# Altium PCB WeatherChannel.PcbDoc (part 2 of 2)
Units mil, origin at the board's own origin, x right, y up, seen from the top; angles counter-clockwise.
Board outline 4050 x 7300 mil, 2 copper layers (Top Layer, Bottom Layer); 129 components, 144 nets, 770 pads, 170 vias.
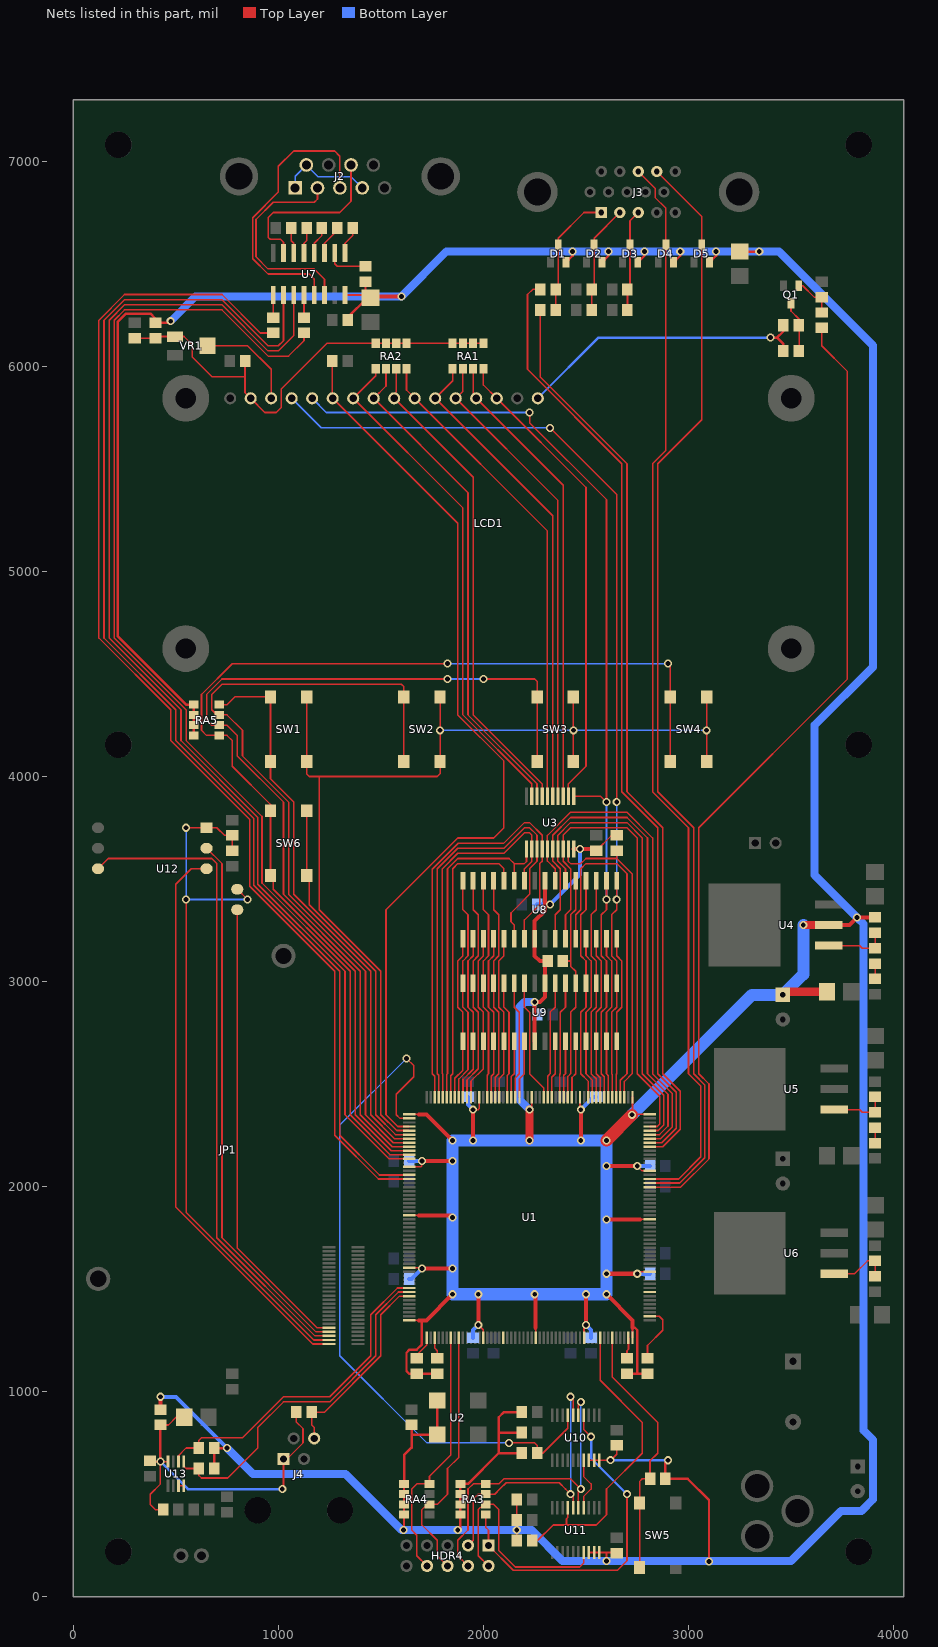
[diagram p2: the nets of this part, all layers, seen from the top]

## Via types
v1: diameter 39.37, hole 23.62, Top Layer to Bottom Layer, 170 vias

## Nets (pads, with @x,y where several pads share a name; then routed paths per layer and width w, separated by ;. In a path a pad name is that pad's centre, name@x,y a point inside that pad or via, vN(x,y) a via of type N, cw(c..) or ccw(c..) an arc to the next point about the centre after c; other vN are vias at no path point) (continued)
JTAG_NEXUS_TDO: HDR4.6 RA4.2 U1.165 | length 1294.2
  Top Layer w7.87: HDR4.6@1825,175 HDR4.6@1825,150 1775,200 1775,275 1700,350 1700,425 1725,450 RA4.2@1737,450 1775,450 1825,500 1825,625 1880.51,680.51 U1.165@1880.51,1263.39
JTAG_NEXUS_TMS: HDR4.8 RA4.4 U1.163 | length 1259.9
  Top Layer w7.87: HDR4.8@1725,150 1675,200 1675,300 1650,325 1650,525 1675,550 RA4.4@1737,550 1737,587 1841.14,691.14 U1.163@1841.14,1263.39
KP_COL0: RA5.4 SW1.3 SW1.4 U1.111 | length 2742.1
  Top Layer w7.87: RA5.4@712,4350 750,4350 787.87,4387.87 SW1.3@961.81,4387.87 SW1.4@961.81,4072.52 961.81,3988.19 1075,3875 1075,3425 1450,3050 1450,2375 1450,2350 1566.14,2233.86 U1.111@1638.39,2233.86
KP_COL1: RA5.3 SW2.3 SW2.4 U1.112 | length 3987.7
  Top Layer w7.87: SW2.4@1611.81,4072.52 SW2.3@1611.81,4387.87 1611.81,4438.19 1600,4450 725,4450 675,4400 675,4325 700,4300 RA5.3@712,4300 750,4300 825,4225 825,4100 1050,3875 1050,3425 1425,3050 1425,2375 1425,2350 1560.83,2214.17 U1.112@1638.39,2214.17
KP_COL2: RA5.2 SW3.3 SW3.4 U1.113 | length 4745.8
  Top Layer w7.87: U1.113@1638.39,2194.49 1555.51,2194.49 1400,2350 1400,2375 1400,3050 1025,3425 1025,3875 800,4100 800,4200 750,4250 RA5.2@712,4250 675,4250 650,4275 650,4400 725,4475 v1(1825,4475) ; v1(2000,4475) 2250,4475 2261.81,4463.19 SW3.3@2261.81,4387.87 SW3.4@2261.81,4072.52
  Bottom Layer w7.87: v1(1825,4475) v1(2000,4475)
KP_COL3: RA5.1 SW4.3 SW4.4 SW6.3 SW6.4 U1.114 | length 5574.7
  Top Layer w7.87: SW6.4@961.81,3517.52 975,3504.33 975,3450 1375,3050 1375,2375 1375,2350 1550.2,2174.8 U1.114@1638.39,2174.8 ; SW6.4@961.81,3522.52 SW6.3@961.81,3837.87 ; SW6.3@961.81,3832.87 961.81,3863.19 775,4050 775,4175 750,4200 RA5.1@712,4200 650,4200 625,4225 625,4400 775,4550 v1(1825,4550) ; v1(2900,4550) 2911.81,4538.19 SW4.3@2911.81,4387.87 SW4.4@2911.81,4072.52
  Bottom Layer w7.87: v1(1825,4550) v1(2900,4550)
KP_ROW0: SW1.1 SW1.2 SW2.1 SW2.2 SW3.1 SW3.2 SW4.1 SW4.2 U1.109 | length 5286.3
  Top Layer w7.87: SW1.1@1138.58,4387.87 SW1.2@1138.58,4072.52 1138.58,4011.42 1150,4000 1775,4000 1788.58,4013.58 SW2.2@1788.58,4072.52 SW2.1@1788.58,4387.87 ; 1200,4000 1200,3350 1500,3050 1500,2375 1500,2350 1576.77,2273.23 U1.109@1638.39,2273.23 ; SW3.2@2438.58,4072.52 SW3.1@2438.58,4387.87 ; SW4.2@3088.58,4072.52 SW4.1@3088.58,4387.87
  Bottom Layer w7.87: v1(1788.58,4225) v1(2438.58,4225) v1(3088.58,4225)
KP_ROW1: U1.8
KP_ROW2: U1.176
KP_ROW3: SW6.1 SW6.2 U1.110 | length 1825.6
  Top Layer w7.87: SW6.2@1138.58,3517.52 1150,3506.1 1150,3375 1475,3050 1475,2375 1475,2350 1571.46,2253.54 U1.110@1638.39,2253.54 ; SW6.2@1138.58,3522.52 SW6.1@1138.58,3837.87
LCD_BCKL: R9.1 U1.34 | length 4770.7
  Top Layer w7.87: U1.34@2811.61,1997.64 2962.64,1997.64 3100,2135 3100,2500 3050,2550 3050,3750 3775,4475 3775,5975 3650,6100 R9.1@3650,6187.6
LCD_D0: LCD1.7 RA2.1 U3.9 | length 2490.2
  Top Layer w7.87: RA2.1@1475,5988 1475,5954 LCD1.7@1365,5844 1900,5309 1900,4300 2235.43,3964.57 U3.9@2235.43,3903.94
LCD_D1: LCD1.8 RA2.2 U3.8 | length 2438.6
  Top Layer w7.87: RA2.2@1525,5988 1525,5904 LCD1.8@1465,5844 1925,5384 1925,4300 2261.02,3963.98 U3.8@2261.02,3903.94
LCD_D2: LCD1.9 RA2.3 U3.7 | length 2387.3
  Top Layer w7.87: LCD1.9@1550,5850 1575,5875 RA2.3@1575,5988 ; LCD1.9@1565,5844 1950,5459 1950,4300 2286.61,3963.39 U3.7@2286.61,3903.94
LCD_D3: LCD1.10 RA2.4 U3.6 | length 2368.7
  Top Layer w7.87: RA2.4@1625,5988 1625,5884 LCD1.10@1665,5844 2312.2,5196.8 U3.6@2312.2,3903.94
LCD_D4: LCD1.11 RA1.1 U3.5 | length 2356.5
  Top Layer w7.87: RA1.1@1850,5988 1850,5929 LCD1.11@1765,5844 2337.8,5271.2 U3.5@2337.8,3903.94
LCD_D5: LCD1.12 RA1.2 U3.4 | length 2305
  Top Layer w7.87: RA1.2@1900,5988 1900,5879 LCD1.12@1865,5844 2363.39,5345.61 U3.4@2363.39,3903.94
LCD_D6: LCD1.13 RA1.3 U3.3 | length 2265.9
  Top Layer w7.87: RA1.3@1950,5988 1950,5859 LCD1.13@1965,5844 2388.98,5420.02 U3.3@2388.98,3903.94
LCD_D7: LCD1.14 RA1.4 U3.2 | length 2326.6
  Top Layer w7.87: RA1.4@2000,5988 2000,5909 LCD1.14@2065,5844 2500,5409 2500,4050 2414.57,3964.57 U3.2@2414.57,3903.94
LCD_E: LCD1.6 R5.1 U1.108 | length 4496.2
  Top Layer w7.87: LCD1.6@1262.6,5846.4 R5.1@1262.6,6025 ; LCD1.6@1265,5844 1875,5234 1875,4300 2100,4075 2100,3750 2050,3700 1875,3700 1725,3550 1525,3350 1525,2350 1582.09,2292.91 U1.108@1638.39,2292.91
LCD_EDATA: R6.1 U1.55 U3.19 | length 1558.3
  Top Layer w7.87: U3.19@2414.57,3646.06 2414.57,3585.43 2425,3575 2475,3575 2500,3600 2650,3600 ; R6.1@2650,3637.6 2650,3600 ; U1.55@2687.6,2436.61 2687.6,2512.6 2725,2550 2725,3525 2650,3600
NetC14_1: C14.1 U7.1 | length 138.1
  Top Layer w7.87: U7.1@1325,6552.36 1325,6600 1362.4,6637.4 C14.1@1362.4,6675
NetC14_2: C14.2 U7.3 | length 148.6
  Top Layer w7.87: U7.3@1225,6552.36 1225,6600 1287.6,6662.6 C14.2@1287.6,6675
NetC15_2: C15.2 U7.2 | length 207.6
  Top Layer w7.87: U7.2@1275,6552.36 1275,6500 1287.6,6487.4 C15.2@1425,6487.4
NetC16_1: C16.1 U7.4 | length 138.1
  Top Layer w7.87: U7.4@1175,6552.36 1175,6600 1212.4,6637.4 C16.1@1212.4,6675
NetC16_2: C16.2 U7.5 | length 127.9
  Top Layer w7.87: U7.5@1125,6552.36 1125,6600 1137.6,6612.6 C16.2@1137.6,6675
NetC17_1: C17.1 U7.6 | length 127.9
  Top Layer w7.87: C17.1@1062.4,6675 1062.4,6612.6 1075,6600 U7.6@1075,6552.36
NetC41_1: C41.1 C42.1 JP1.2 U12.1 U12.7 | length 3516.3
  Top Layer w7.87: v1(550,3400) 550,1875 1173.03,1251.97 JP1.2@1246.46,1251.97 ; v1(550,3750) U12.1@650,3750 700,3750 737.4,3712.6 C42.1@775,3712.6 C41.1@775,3637.4 ; U12.7@799.61,3450 849.61,3400 v1(850,3400)
  Bottom Layer w7.87: v1(550,3750) v1(550,3400) v1(850,3400)
NetD1_3: D1.3 J3.1 R31.2 R34.2 | length 617
  Top Layer w7.87: R31.2@2352.4,6275 R34.2@2352.4,6375 2365,6387.6 D1.3@2365,6593.31 2365,6625 2490,6750 J3.1@2575,6750
NetD2_3: D2.3 J3.2 R32.2 R35.2 | length 532.1
  Top Layer w7.87: R32.2@2527.4,6275 R35.2@2527.4,6375 2540,6387.6 D2.3@2540,6593.31 2540,6624.84 J3.2@2665.16,6750
NetD3_3: D3.3 J3.3 R33.2 R36.2 | length 496.9
  Top Layer w7.87: R33.2@2702.4,6275 R36.2@2702.4,6375 2715,6387.6 D3.3@2715,6593.31 2715,6709.68 J3.3@2755.32,6750
NetJ2_1: J2.1 J2.4 J2.6 | length 457.5
  Bottom Layer w7.87: J2.1@1081.89,6870.08 1081.89,6927.36 J2.6@1136.42,6981.89 1193.31,6925 1354.13,6925 J2.4@1409.05,6870.08 ; J2.1@1104.92,6845.08 J2.1@1109.05,6845.08
NetJP1_1: JP1.1 U12.3 | length 2779.1
  Top Layer w7.87: U12.3@650,3550 575,3550 500,3475 500,1900 1167.72,1232.28 JP1.1@1246.46,1232.28
NetJP1_3: JP1.3 U12.6 | length 3180.2
  Top Layer w7.87: U12.6@120.47,3550 170.47,3600 675,3600 700,3575 700,1750 1178.35,1271.65 JP1.3@1246.46,1271.65
NetJP1_4: JP1.4 U12.2 | length 2642.5
  Top Layer w7.87: U12.2@650,3650 725,3575 725,1750 1183.66,1291.34 JP1.4@1246.46,1291.34
NetJP1_5: JP1.5 U12.8 | length 2257.7
  Top Layer w7.87: U12.8@799.61,3350 799.61,1700.39 1188.98,1311.02 JP1.5@1246.46,1311.02
NetLCD1_3: LCD1.3 VR1.W | length 499.9
  Top Layer w7.87: VR1.W@653.74,6100 850,6100 965,5985 LCD1.3@965,5844
NetLCD1_16: LCD1.16 R7.1 R8.1 | length 1454
  Top Layer w11.81: v1@3410,6150 v1(3400,6140) 3431.5,6140 ; R8.1@3462.6,6075 3462.6,6108.9 3431.5,6140 ; R7.1@3462.6,6200 3462.6,6171.1 3431.5,6140
  Bottom Layer w11.81: LCD1.16@2265,5844 2561,6140 v1(3400,6140)
NetQ1_1: Q1.1 R9.2 R10.2 | length 210.9
  Top Layer w7.87: Q1.1@3537.4,6393.31 3556.69,6393.31 3612.4,6337.6 R10.2@3650,6337.6 R9.2@3650,6262.4
NetQ1_3: Q1.3 R7.2 R8.2 | length 248.3
  Top Layer w7.87: Q1.3@3500,6306.69 3500,6269.29 3540,6229.29 3540,6197.4 R8.2@3540,6075
NetR13_2: R13.2 R16.1 U4.1 | length 305.4
  Top Layer w7.87: U4.1@3685,3175 3835,3175 3847.6,3162.4 R16.1@3910,3162.4 R13.2@3910,3237.6
NetR14_2: R14.2 R18.1 U5.1 | length 280.4
  Top Layer w7.87: U5.1@3710,2375 3835,2375 3847.6,2362.4 R18.1@3910,2362.4 R14.2@3910,2437.6
NetR15_2: R15.2 R20.1 U6.1 | length 301.1
  Top Layer w7.87: U6.1@3710,1575 3810,1575 3872.6,1637.6 R15.2@3910,1637.6 R20.1@3910,1562.4
NetR16_2: R16.2 R17.1 | length 75.2
  Top Layer w7.87: R17.1@3910,3012.4 R16.2@3910,3087.6
NetR18_2: R18.2 R19.1 | length 75.2
  Top Layer w7.87: R19.1@3910,2212.4 R18.2@3910,2287.6
NetR21_2: R21.2 U7.12 | length 110.2
  Top Layer w7.87: R21.2@1125,6237.4 U7.12@1125,6347.64
NetR22_2: R22.2 U7.9 | length 110.2
  Top Layer w7.87: R22.2@975,6237.4 U7.9@975,6347.64
NetU10_17: U10.17 U11.4 | length 261.8
  Top Layer w7.87: U11.4@2488.39,434.25 2488.39,488.39 2525,525 2525,550 2488.39,586.61 U10.17@2488.39,665.75
NetU13_3: U13.3 U13.4 | length 25.6
  Top Layer w7.87: U13.3@512.8,540.95 U13.4@538.39,540.95
PROGRAM: R26.2 U1.106 U10.7 | length 3423.5
  Top Layer w7.87: v1(1625,2625) 1660,2590 1660,2535 1575,2450 1575,2350 1592.72,2332.28 U1.106@1638.39,2332.28 ; v1(2125,750) 2250,750 2262.4,737.6 R26.2@2262.4,700 2290,700 2411.61,821.61 U10.7@2411.61,884.25
  Bottom Layer w7.87: v1(1625,2625) 1300,2300 1300,1175 1725,750 v1(2125,750)
PROGRAM_PR: R29.2 U1.200 U11.7 | length 1522.4
  Top Layer w7.87: R29.2@2237.4,275 2265,275 2340,350 2385,350 2550,350 2600,400 2600,525 2775,700 2775,850 2569.49,1055.51 U1.200@2569.49,1263.39 ; 2405,350 2405,380 2411.61,386.61 U11.7@2411.61,434.25
RAM0_DATA0: U1.99 U3.11 U8.11 | length 1679.3
  Top Layer w7.87: U1.99@1821.46,2436.61 1821.46,2546.46 1825,2550 1825,3550 1875,3600 2125,3600 2150,3575 ; U8.11@2150,3491.73 2150,3575 ; U3.11@2209.84,3646.06 2209.84,3584.84 2200,3575 2150,3575
RAM0_DATA1: U1.100 U3.12 U8.10 | length 1863.9
  Top Layer w7.87: U1.100@1801.77,2436.61 1801.77,2548.23 1800,2550 1800,3550 1875,3625 2100,3625 2200,3725 2225,3725 2235.43,3714.57 2235.43,3585.43 2200,3550 U8.10@2200,3491.73
RAM0_DATA2: U1.101 U3.13 U8.22 | length 2264.9
  Top Layer w7.87: U1.101@1782.09,2436.61 1782.09,2542.91 1775,2550 1775,3550 1875,3650 2100,3650 2200,3750 2225,3750 2261.02,3713.98 2261.02,3586.02 2225,3550 2225,3425 2134.25,3334.25 2134.25,3290.93 2150,3275.18 U8.22@2150,3208.27
RAM0_DATA3: U1.102 U3.14 U8.23 | length 2314.9
  Top Layer w7.87: U1.102@1762.4,2436.61 1762.4,2537.6 1750,2550 1750,3547.27 1875,3672.27 1875,3675 2100,3675 2200,3775 2225,3775 2286.61,3713.39 2286.61,3586.61 2275,3575 2275,3375 2200,3300 U8.23@2200,3208.27
RAM0_DATA4: U1.46 U3.15 U8.7 | length 2428.4
  Top Layer w7.87: U8.7@2350,3491.73 2350,3550 2312.2,3587.8 2312.2,3712.2 2425,3825 2700,3825 2825,3700 2825,2550 2920,2455 2920,2290 2863.86,2233.86 U1.46@2811.61,2233.86
RAM0_DATA5: U1.47 U3.16 U8.26 | length 2622
  Top Layer w7.87: U8.26@2350,3208.27 2350,3325 2375,3350 2375,3550 2337.8,3587.2 2337.8,3712.8 2425,3800 2700,3800 2800,3700 2800,2550 2900,2450 2900,2295 2858.54,2253.54 U1.47@2811.61,2253.54
RAM0_DATA6: U1.48 U3.17 U8.6 | length 2228
  Top Layer w7.87: U8.6@2400,3491.73 2400,3550 2363.39,3586.61 2363.39,3713.39 2425,3775 2700,3775 2775,3700 2775,2550 2880,2445 2880,2300 2853.23,2273.23 U1.48@2811.61,2273.23
RAM0_DATA7: U1.49 U3.18 U8.27 | length 2421.6
  Top Layer w7.87: U8.27@2400,3208.27 2400,3325 2425,3350 2425,3550 2388.98,3586.02 2388.98,3713.98 2425,3750 2700,3750 2750,3700 2750,2550 2860,2440 2860,2305 2847.91,2292.91 U1.49@2811.61,2292.91
RAM0_OE: U1.56 U8.28 | length 1709.8
  Top Layer w7.87: U8.28@2450,3208.27 2450,3325 2475,3350 2475,3550 2500,3575 2650,3575 2700,3525 2700,2550 2667.91,2517.91 U1.56@2667.91,2436.61
RAM0_WE: U1.98 U8.12 | length 1446
  Top Layer w7.87: U1.98@1841.14,2436.61 1841.14,2541.14 1850,2550 1850,3550 1875,3575 2075,3575 2100,3550 U8.12@2100,3491.73
RAM1_DATA0: U1.71 U9.6 | length 566.5
  Top Layer w7.87: U1.71@2372.64,2436.61 2372.64,2547.64 2375,2550 2375,2850 2400,2875 U9.6@2400,2991.73
RAM1_DATA1: U1.74 U9.7 | length 570.2
  Top Layer w7.87: U1.74@2313.58,2436.61 2313.58,2538.58 2325,2550 2325,2850 2350,2875 U9.7@2350,2991.73
RAM1_DATA2: U1.75 U9.10 | length 594
  Top Layer w7.87: U9.10@2200,2991.73 2200,2875 2225,2850 2225,2550 2293.9,2481.1 U1.75@2293.9,2436.61
RAM1_DATA3: U1.82 U9.11 | length 573.3
  Top Layer w7.87: U9.11@2150,2991.73 2150,2875 2175,2850 2175,2550 2156.1,2531.1 U1.82@2156.1,2436.61
RAM1_DATA4: U1.83 U9.22 | length 277.3
  Top Layer w7.87: U1.83@2136.42,2436.61 2136.42,2536.42 2150,2550 U9.22@2150,2708.27
RAM1_DATA5: U1.81 U9.23 | length 281.7
  Top Layer w7.87: U1.81@2175.79,2436.61 2175.79,2525.79 2200,2550 U9.23@2200,2708.27
RAM1_DATA6: U1.73 U9.26 | length 278.6
  Top Layer w7.87: U1.73@2333.27,2436.61 2333.27,2533.27 2350,2550 U9.26@2350,2708.27
RAM1_DATA7: U1.70 U9.27 | length 274.8
  Top Layer w7.87: U1.70@2392.32,2436.61 2392.32,2542.32 2400,2550 U9.27@2400,2708.27
RAM1_OE: U1.68 U9.28 | length 279.2
  Top Layer w7.87: U1.68@2431.69,2436.61 2431.69,2531.69 2450,2550 U9.28@2450,2708.27
RAM1_WE: U1.84 U9.12 | length 568.9
  Top Layer w7.87: U9.12@2100,2991.73 2100,2875 2125,2850 2125,2550 2116.73,2541.73 U1.84@2116.73,2436.61
RAM_ADDR0: LCD1.4 U1.58 U8.1 U9.1 | length 4841.9
  Top Layer w7.87: v1(2325,5700) 2650,5375 v1(2650,3875) ; U1.58@2628.54,2436.61 2628.54,2546.46 2625,2550 2625,2850 2650,2875 2650,3100 2625,3125 2625,3325 2650,3350 U8.1@2650,3491.73
  Bottom Layer w7.87: LCD1.4@1065,5844 1209,5700 v1(2325,5700) ; v1(2650,3400) v1(2650,3875)
RAM_ADDR1: LCD1.5 U1.60 U3.1 U8.2 U9.2 | length 4882.8
  Top Layer w7.87: v1(2225,5775) 2225,5725 2600,5350 v1(2600,3875) 2571.06,3903.94 U3.1@2440.16,3903.94 ; U1.60@2589.17,2436.61 2589.17,2535.83 2575,2550 2575,2850 2600,2875 2600,3100 2575,3125 2575,3325 2600,3350 U8.2@2600,3491.73
  Bottom Layer w7.87: LCD1.5@1165,5844 1234,5775 v1(2225,5775) ; v1(2600,3400) v1(2600,3875)
RAM_ADDR2: U1.62 U8.3 U9.3 | length 1096.5
  Top Layer w7.87: U1.62@2549.8,2436.61 2549.8,2525.2 2525,2550 2525,2850 2550,2875 2550,3100 2525,3125 2525,3325 2550,3350 U8.3@2550,3491.73
RAM_ADDR3: U1.64 U8.4 U9.4 | length 1100.9
  Top Layer w7.87: U8.4@2500,3491.73 2500,3350 2475,3325 2475,3125 2500,3100 2500,2875 2475,2850 2475,2550 2510.43,2514.57 U1.64@2510.43,2436.61
RAM_ADDR4: U1.87 U8.13 U9.13 | length 1093.4
  Top Layer w7.87: U8.13@2050,3491.73 2050,3350 2075,3325 2075,3125 2050,3100 2050,2875 2075,2850 2075,2550 2057.68,2532.68 U1.87@2057.68,2436.61
RAM_ADDR5: U1.89 U8.14 U9.14 | length 1089
  Top Layer w7.87: U8.14@2000,3491.73 2000,3350 2025,3325 2025,3125 2000,3100 2000,2875 2025,2850 2025,2550 2018.31,2543.31 U1.89@2018.31,2436.61
RAM_ADDR6: U1.94 U8.15 U9.15 | length 1109
  Top Layer w7.87: U1.94@1919.88,2436.61 1919.88,2519.88 1975,2575 1975,2850 1950,2875 1950,3100 1975,3125 1975,3325 1950,3350 U8.15@1950,3491.73
RAM_ADDR7: U1.96 U8.16 U9.16 | length 1112.9
  Top Layer w7.87: U1.96@1880.51,2436.61 1880.51,2525.05 1925,2569.54 1925,2850 1900,2875 1900,3100 1925,3125 1925,3325 1900,3350 U8.16@1900,3500
RAM_ADDR8: U1.97 U8.17 U9.17 | length 808.6
  Top Layer w7.87: U1.97@1860.83,2436.61 1860.83,2527.64 1900,2566.81 1900,2850 1875,2875 1875,3100 1900,3125 U8.17@1900,3208.27
RAM_ADDR9: U1.95 U8.18 U9.18 | length 813
  Top Layer w7.87: U1.95@1900.2,2436.61 1900.2,2522.47 1950,2572.27 1950,2850 1925,2875 1925,3100 1950,3125 U8.18@1950,3208.27
RAM_ADDR10: U1.93 U8.19 U9.19 | length 817.4
  Top Layer w7.87: U1.93@1939.57,2436.61 1939.57,2514.57 2000,2575 2000,2850 1975,2875 1975,3100 2000,3125 U8.19@2000,3208.27
RAM_ADDR11: U1.88 U8.20 U9.20 | length 797.3
  Top Layer w7.87: U1.88@2037.99,2436.61 2037.99,2537.99 2050,2550 2050,2850 2025,2875 2025,3100 2050,3125 U8.20@2050,3208.27
RAM_ADDR12: U1.86 U8.21 U9.21 | length 801.7
  Top Layer w7.87: U1.86@2077.36,2436.61 2077.36,2527.36 2100,2550 2100,2850 2075,2875 2075,3100 2100,3125 U8.21@2100,3208.27
RAM_ADDR13: U1.63 U8.29 U9.29 | length 804.8
  Top Layer w7.87: U8.29@2500,3208.27 2500,3125 2525,3100 2525,2875 2500,2850 2500,2550 2530.12,2519.88 U1.63@2530.12,2436.61
RAM_ADDR14: U1.61 U8.30 U9.30 | length 800.4
  Top Layer w7.87: U8.30@2550,3208.27 2550,3125 2575,3100 2575,2875 2550,2850 2550,2550 2569.49,2530.51 U1.61@2569.49,2436.61
RAM_ADDR15: U1.59 U8.31 U9.31 | length 796
  Top Layer w7.87: U8.31@2600,3208.27 2600,3125 2625,3100 2625,2875 2600,2850 2600,2550 2608.86,2541.14 U1.59@2608.86,2436.61
RAM_ADDR16: U1.57 U8.32 U9.32 | length 793.1
  Top Layer w7.87: U1.57@2648.23,2436.61 2648.23,2548.23 2650,2550 2650,2850 2675,2875 2675,3100 2650,3125 U8.32@2650,3208.27
RAM_CS: R23.2 U1.69 U8.5 U9.5 | length 1129.2
  Top Layer w7.87: R23.2@2387.4,3100 2425,3100 ; U1.69@2412.01,2436.61 2412.01,2537.01 2425,2550 2425,2850 2450,2875 2450,3050 2425,3075 2425,3325 2450,3350 U8.5@2450,3491.73
RED0: R31.1 U1.44 | length 4461.5
  Top Layer w7.87: R31.1@2277.6,6275 2277.6,5947.4 2700,5525 2700,5125 2700,3925 2875,3750 2875,2550 2960,2465 2960,2280 2874.49,2194.49 U1.44@2811.61,2194.49
RED1: R34.1 U1.45 | length 4596
  Top Layer w7.87: R34.1@2277.6,6375 2240,6375 2215,6350 2215,5985 2675,5525 2675,5125 2675,3925 2850,3750 2850,2550 2940,2460 2940,2285 2869.17,2214.17 U1.45@2811.61,2214.17
RS_CTS: R22.1 U1.121 | length 5882.4
  Top Layer w7.87: R22.1@975,6162.6 912.4,6162.6 725,6350 250,6350 125,6225 125,4675 475,4325 475,4175 860,3790 860,3465 1275,3050 1275,2300 1275,2250 1487.99,2037.01 U1.121@1638.39,2037.01
RS_RTS: U1.120 U7.10 | length 6112.4
  Top Layer w7.87: U7.10@1025,6347.64 1025,6125 1000,6100 950,6100 725,6325 250,6325 150,6225 150,4675 500,4325 500,4175 880,3795 880,3470 1300,3050 1300,2375 1300,2300 1300,2250 1493.31,2056.69 U1.120@1638.39,2056.69
RS_RX: R21.1 U1.115 | length 5828
  Top Layer w7.87: R21.1@1125,6162.6 1125,6125 1050,6050 950,6050 725,6275 250,6275 200,6225 200,4675 550,4325 550,4175 920,3805 920,3480 1350,3050 1350,2375 1350,2350 1544.88,2155.12 U1.115@1638.39,2155.12
RS_TX: U1.116 U7.11 | length 6006.6
  Top Layer w7.87: U7.11@1075,6347.64 1075,6150 1000,6075 950,6075 725,6300 250,6300 175,6225 175,4675 525,4325 525,4175 900,3800 900,3475 1325,3050 1325,2375 1325,2350 1539.57,2135.43 U1.116@1638.39,2135.43
RTS: J2.8 U7.7 | length 847.8
  Top Layer w7.87: U7.7@1025,6552.36 1025,6605 1010,6620 960,6620 950,6630 950,6725 975,6750 1300,6750 1354.53,6804.53 J2.8@1354.53,6981.89
RX: J2.3 U7.13 | length 1416.9
  Top Layer w7.87: U7.13@1175,6347.64 1175,6425 1150,6450 950,6450 875,6525 875,6725 1000,6850 1000,6975 1075,7050 1275,7050 1300,7025 J2.3@1300,6870.08
SCL: R37.2 U1.149 U13.5 | length 1717.8
  Top Layer w7.87: U13.5@538.39,659.06 538.39,636.61 550,625 R37.2@612.6,625 612.6,591.06 625,578.66 723.66,578.66 753.66,578.66 900,725 900,825 1025,950 1250,950 1475,1175 1475,1375 1585.83,1485.83 U1.149@1638.39,1485.83
SDA: R38.2 U1.148 U13.6 | length 1632.2
  Top Layer w7.87: U13.6@512.8,659.06 512.8,687.8 550,725 R38.2@612.6,725 612.6,762.6 625,775 825,775 900,850 1025,975 1250,975 1450,1175 1450,1375 1580.51,1505.51 U1.148@1638.39,1505.51
SPEED: J4.4 R40.2 U1.150 | length 960.8
  Top Layer w7.87: J4.4@1175,772.05 1175,825 1162.4,837.6 R40.2@1162.4,900 1225,900 1500,1175 1500,1375 1591.14,1466.14 U1.150@1638.39,1466.14
TCK: R3.2 U1.207 | length 104
  Top Layer w7.87: R3.2@2700,1162.4 2700,1200 2707.28,1207.28 U1.207@2707.28,1263.39
TCK_HARD: HDR4.3 RA3.3 U10.6 U11.6 | length 1408.5
  Top Layer w7.87: HDR4.3@1925,250 1950,275 1950,475 1975,500 RA3.3@2012,500 2055,500 2080,525 2110.75,555.75 2369.25,555.75 2400,525 v1(2425,500) 2437.2,487.8 U11.6@2437.2,434.25 ; v1(2425,975) 2437.2,962.8 U10.6@2437.2,884.25
  Bottom Layer w7.87: v1(2425,500) v1(2425,975)
TDI: R2.2 U1.159 | length 106.2
  Top Layer w7.87: U1.159@1762.4,1263.39 1762.4,1212.6 1775,1200 R2.2@1775,1162.4
TDI_HARD: HDR4.1 RA3.1 U10.4 | length 1696.3
  Top Layer w7.87: RA3.1@2012,400 2012,338 2025,325 HDR4.1@2025,250 2145.75,129.25 2589.25,129.25 2654.25,129.25 2700,175 2700,240 v1(2700,500) ; U10.4@2488.39,884.25 2488.39,816.61 v1(2525,780)
  Bottom Layer w11.81: v1(2525,780) 2525,675 v1(2700,500)
TDO: R1.2 U1.157 | length 120.9
  Top Layer w7.87: R1.2@1675,1162.4 1675,1178.94 1723.03,1226.97 U1.157@1723.03,1263.39
TDO_HARD: HDR4.2 RA3.2 U11.17 | length 1122.9
  Top Layer w7.87: HDR4.2@2025,150 1975,200 1975,425 2000,450 RA3.2@2012,450 2050,450 2075,425 2075,225 2155,145 2470,145 2488.39,163.39 U11.17@2488.39,215.75
TEST: R30.2 SW5.1 SW5.2 U1.203 | length 1271.7
  Top Layer w7.87: U1.203@2628.54,1263.39 2628.54,1071.46 2850,850 2850,699.8 2812.6,662.4 R30.2@2812.6,575 2775,575 2761.42,561.42 SW5.2@2761.42,457.48 SW5.1@2761.42,142.13
TMS: R4.2 U1.2 | length 289.4
  Top Layer w7.87: R4.2@2800,1162.4 2800,1225 2875,1300 2875,1350 2857.28,1367.72 U1.2@2811.61,1367.72
TMS_HARD: HDR4.4 RA3.4 U10.5 U11.5 | length 1599.4
  Top Layer w7.87: HDR4.4@1925,150 1875,200 1875,275 1925,325 1925,525 1950,550 RA3.4@2012,550 2075,550 2100,575 2425,575 2450,550 v1(2475,525) 2462.8,512.8 U11.5@2462.8,434.25 ; U10.5@2462.8,884.25 2462.8,937.8 v1(2475,950)
  Bottom Layer w7.87: v1(2475,525) v1(2475,950)
TX: J2.2 U7.14 | length 1031.7
  Top Layer w7.87: J2.2@1190.94,6870.08 1190.94,6815.94 1175,6800 975,6800 890.94,6715.94 890.94,6534.06 950,6475 1175,6475 1225,6425 U7.14@1225,6350
VCC: C1.1 C3.1 C4.1 C8.1 C15.1 C18.1 C19.1 C20.1 C21.1 C22.2 C23.2 C24.1 C25.1 C26.1 C27.1 C28.1 C29.1 C30.1 C31.1 C40.1 D1.2 D2.2 D3.2 D4.2 D5.2 R1.1 R2.1 R3.1 R4.1 R6.2 R12.1 R13.1 R23.1 R24.1 R25.1 R26.1 R27.1 R28.1 R29.1 R30.1 R37.1 R38.1 R42.1 RA3.5 RA3.6 RA3.7 RA3.8 RA4.5 RA4.6 RA4.7 RA4.8 RA5.5 RA5.6 RA5.7 RA5.8 U1.13 U1.26 U1.38 U1.52 U1.53 U1.66 U1.78 U1.91 U1.105 U1.118 U1.130 U1.143 U1.156 U1.171 U1.184 U1.196 U1.208 U2.1 U2.4 U3.20 U4.2 U7.16 U8.8 U8.24 U9.8 U9.24 U10.18 U10.19 U10.20 U11.18 U11.19 U11.20 | length 32857.5
  Top Layer w7.87: v1(1610.23,325) 1613,327.77 RA4.8@1613,400 RA4.5@1613,550 ; U1.156@1638.39,1348.03 1686.61,1348.03 ; U1.143@1638.39,1603.94 1696.06,1603.94 v1(1700,1600) ; U1.130@1638.39,1859.84 1686.61,1859.84 ; U1.118@1638.39,2096.06 1696.06,2096.06 1700,2100 v1(1700,2125) ; U1.105@1638.39,2351.97 1686.61,2351.97 ; v1(1950,2375) 1975,2375 1978.94,2378.94 U1.91@1978.94,2436.61 ; v1(1975,1325) 1998.62,1301.38 U1.171@1998.62,1263.39 ; R29.1@2162.6,275 R28.1@2162.6,475 ; v1(2225,2375) 2234.84,2384.84 U1.78@2234.84,2436.61 ; U1.184@2254.53,1263.39 2254.53,1311.61 ; U1.66@2471.06,2436.61 2471.06,2378.94 v1(2475,2375) ; U1.196@2490.75,1263.39 2490.75,1315.75 v1(2500,1325) ; U11.18@2513.98,215.75 U11.20@2565.16,215.75 2646.85,215.75 C22.2@2650,212.6 ; U10.18@2513.98,665.75 U10.20@2565.16,665.75 v1(2620.48,665.75) 2650,695.27 C23.2@2650,737.6 ; C3.1@2550,3637.6 2624.8,3712.4 R6.2@2650,3712.4 ; v1(2600,175) 2600,215.75 ; v1(2725,2350) v1@2726.97,2351.97 ; U1.208@2726.97,1263.39 2726.97,1311.61 ; U1.53@2726.97,2436.61 v1@2726.97,2351.97 ; v1(2750,1575) 2759.25,1584.25 U1.13@2811.61,1584.25 ; v1(2750,2100) 2773.62,2076.38 U1.38@2811.61,2076.38 ; 2763.39,1840.16 U1.26@2811.61,1840.16 ; U1.52@2811.61,2351.97 v1@2726.97,2351.97
  Top Layer w11.81: v1(475,6220) 467.4,6212.4 R12.1@400,6212.4 400,6233.26 375.98,6257.28 257.34,6257.28 217.72,6217.66 217.72,4682.34 550.05,4350 RA5.5@588,4350 RA5.8@588,4200 ; R37.1@687.4,625 R38.1@687.4,725 v1(750,725) ; U7.16@1325,6347.64 1436.42,6347.64 C19.1@1450,6334.05 ; C18.1@1337.4,6225 1337.4,6237.4 1434.05,6334.05 C19.1@1450,6334.05 ; C15.1@1425,6412.6 1425,6359.05 C19.1@1450,6334.05 ; RA4.5@1613,550 1613,690.37 1650,727.37 C1.1@1650,837.6 ; 1655.72,790.75 U2.1@1775,790.75 U2.4@1775,956.1 ; 1700,1348.03 1700,1230 1675,1205 1640,1205 1625,1190 1625,1100.39 1637.79,1087.6 R1.1@1675,1087.6 R2.1@1775,1087.6 ; v1(1875,325) 1888,338 RA3.8@1888,400 RA3.5@1888,550 1924.95,550 2074.94,700 ; 2074.94,800 R24.1@2187.6,800 ; R26.1@2187.6,700 2074.94,700 ; R25.1@2187.6,900 2100,900 2074.94,874.95 2074.94,700 ; D1.2@2402.4,6506.69 2435,6539.29 v1(2435,6559.06) ; D2.2@2577.4,6506.69 2610,6539.29 v1(2610,6559.06) ; R3.1@2700,1087.6 R4.1@2800,1087.6 ; 2726.97,1311.61 2738.39,1311.61 2750,1300 2750,1087.6 ; D3.2@2752.4,6506.69 2785,6539.29 v1(2785,6559.06) ; v1(2900,665.35) 2887.4,652.75 R30.1@2887.4,575 2995.86,575 3100,470.86 v1(3100,171.65) ; D4.2@2927.4,6506.69 2960,6539.29 v1(2960,6559.06) ; D5.2@3102.4,6506.69 3135,6539.29 v1(3135,6559.05) ; C40.1@3250,6559.05 3344.05,6559.05 v1(3345,6560)
  Top Layer w19.68: R42.1@425,912.4 v1(425,975) ; C19.1@1455.95,6340 v1(1600,6340) ; 1686.61,1348.03 1723.03,1348.03 v1(1850,1475) ; 1686.61,1859.84 1840.16,1859.84 v1(1850,1850) ; 1686.61,2351.97 1723.03,2351.97 v1(1850,2225) ; v1(1700,1600) v1(1850,1600) ; v1(1700,2125) v1(1850,2125) ; v1(1950,2225) v1(1950,2375) ; v1(1975,1325) v1(1975,1475) ; v1(2250,1475) 2254.53,1470.47 2254.53,1311.61 ; U9.24@2250,2708.27 v1(2250,2900) 2275,2900 2300,2925 2300,3100 2275,3100 2250,3125 2250,3295 2300,3345 U8.8@2300,3491.73 ; 2300,3375 v1(2325,3375) ; U3.20@2440.16,3646.06 v1(2471.06,3646.06) 2541.54,3646.06 C3.1@2550,3637.6 ; v1(2475,2225) v1(2475,2375) ; v1(2500,1325) v1(2500,1475) ; v1(2600,1475) 2726.97,1348.03 2726.97,1311.61 ; v1(2600,1575) v1(2750,1575) ; v1(2600,1840) 2600.16,1840.16 2763.39,1840.16 ; v1(2600,2100) v1(2750,2100) ; U4.2@3685,3275 3785,3275 v1(3822.4,3312.4) R13.1@3910,3312.4
  Top Layer w39.37: v1(2225,2225) v1(2225,2375) ; C4.1@3460,2935 3475,2950 C8.1@3675.95,2950 ; v1(3560,3275) U4.2@3685,3275
  Top Layer w59.06: v1(2600,2225) v1(2725,2350)
  Bottom Layer w7.87: v1@2440,6560 v1@2440.95,6559.05 ; v1@2965,6559.05 v1@2965,6560
  Bottom Layer w11.81: v1(2620.48,665.75) 2899.6,665.75 v1(2900,665.35)
  Bottom Layer w19.68: v1(425,975) 500,975 v1(750,725) ; C24.1@1637.4,1550 1650,1550 v1(1700,1600) ; C31.1@1637.4,2125 v1(1700,2125) ; C27.1@1925,2437.6 1925,2400 v1(1950,2375) ; C28.1@1950,1262.4 1950,1300 v1(1975,1325) ; C20.1@2250,2837.4 v1(2250,2900) ; C21.1@2262.4,3375 v1(2325,3375) 2471.06,3521.06 v1(2471.06,3646.06) ; v1(2475,2375) 2537.6,2437.6 C25.1@2550,2437.6 ; v1(2500,1325) 2525,1300 C29.1@2525,1262.4 ; v1(2750,1575) C30.1@2812.6,1575 ; v1(2750,2100) C26.1@2812.6,2100
  Bottom Layer w39.37: v1(475,6220) 595,6340 v1(1600,6340) 1819.06,6559.06 2975.94,6559.06 3440.95,6559.05 3899.2,6100.8 ; v1(750,725) 876.98,598.02 924.02,598.02 1326.98,598.02 1600,325 v1(2162.6,325) 2235.82,325 2385.82,175 3500,175 3743.5,418.5 3843.5,418.5 3900,475 3900,765.15 3854.32,810.83 3854.32,3280.49 v1(3822.4,3312.4) 3614.95,3519.85 3614.95,4250 3899.2,4534.25 ; v1(2225,2375) 2175,2425 2175,2875 2200,2900 v1(2250,2900) ; 3900,4532.66 3900,6099.21
  Bottom Layer w59.06: v1(2725,2350) 3310,2935 C4.1@3460,2935 3560,3035 v1(3560,3275) ; v1(1850,1475) v1(2600,1475) v1(2600,2225) v1(1850,2225) v1(1850,1475)
VCC_LCD: C2.1 LCD1.2 R11.2 R12.2 RA1.5 RA1.6 RA1.7 RA1.8 RA2.5 RA2.6 RA2.7 RA2.8 VR1.CW | length 2204.9
  Top Layer w7.87: R11.2@300,6137.6 R12.2@400,6137.6 407.68,6145.28 VR1.CW@496.26,6145.28 539.72,6145.28 580,6105 580,6045 675,5950 837.4,5950 ; C2.1@837.4,6025 837.4,5871.6 LCD1.2@865,5844 934,5775 990,5775 1015,5800 1015,5890 1237,6112 RA2.8@1475,6112 RA1.5@2000,6112
VCCA: C43.1 C44.1 J4.1 R40.1 R41.1 R42.2 U13.8 | length 1790.6
  Top Layer w7.87: C43.1@375,662.4 378.35,659.06 U13.8@461.61,659.06 ; v1(425,659.06) 425,550 375,500 375,450 400,425 R41.1@437.6,425 ; R42.2@425,837.6 463.94,837.6 501.34,875 C44.1@540.95,875 ; v1(1019.29,525) 1025,530.71 J4.1@1025,672.05 1042.05,672.05 1120,750 1120,820 1087.6,852.4 R40.1@1087.6,900
  Top Layer w11.81: v1(425,659.06) R42.2@425,837.6
  Bottom Layer w11.81: v1(425,659.06) 559.06,525 v1(1019.29,525)
VGA_HSYN: D4.3 J3.13 U1.36 | length 5278.2
  Top Layer w7.87: J3.13@2755.32,6950 2837,6868.32 2837,6823.63 2890,6770.63 D4.3@2890,6593.31 2890,5590 2825,5525 2825,5125 2825,3925 3000,3750 3000,2550 3060,2490 3060,2255 3060,2145 2952.01,2037.01 U1.36@2811.61,2037.01
VGA_VSYN: D5.3 J3.14 U1.35 | length 5404.5
  Top Layer w7.87: U1.35@2811.61,2017.32 2957.32,2017.32 3080,2140 3080,2495 3025,2550 3025,3750 2850,3925 2850,5125 2850,5525 3065,5740 D5.3@3065,6593.31 3065,6730.47 J3.14@2845.47,6950
pads on no net: J2.9 J3.4 J3.9 J3.11 J3.12 J3.15 J4.MH1 J4.MH2 JP1.0 JP1.7 JP1.8 JP1.9 JP1.10 JP1.11 JP1.12 JP1.14 JP1.16 JP1.18 JP1.19 JP1.20 JP1.31 JP1.32 JP1.33 JP1.35 JP1.36 JP1.38 JP1.39 JP1.40 JP1.43 JP1.44 JP1.45 JP1.46 JP1.47 JP1.48 JP1.49 JP1.50 LCD1.M1 LCD1.M2 LCD1.M3 LCD1.M4 U1.3 U1.4 U1.5 U1.6 U1.7 U1.9 U1.10 U1.11 U1.15 U1.16 U1.17 U1.18 U1.20 U1.21 U1.22 U1.23 U1.24 U1.27 U1.29 U1.30 U1.31 U1.33 U1.77 U1.80 U1.122 U1.123 U1.129 U1.132 U1.133 U1.134 U1.135 U1.136 U1.138 U1.139 U1.140 U1.141 U1.151 U1.152 U1.154 U1.160 U1.161 U1.162 U1.167 U1.168 U1.169 U1.173 U1.174 U1.175 U1.178 U1.179 U1.180 U1.181 U1.185 U1.187 U1.188 U1.189 U1.191 U1.192 U1.193 U1.194 U1.204 U1.205 U1.206 U4.4 U5.4 U6.4 U10.2 U10.9 U10.12 U10.13 U10.14 U10.15 U10.16 U11.2 U11.9 U11.12 U11.13 U11.14 U11.15 U11.16 U12.5

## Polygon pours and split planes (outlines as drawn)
GND on Top Layer "Top Layer-GND" (solid, remove dead copper, pour order 1001): 73.11,7225 75,1065 1260,1065 1260,75 3973.11,75 3973.11,7225
AGND on Top Layer "Top Layer-AGND" (solid, remove dead copper, pour order 1000): 75,1035 75,75 1235,75 1235,1035
GND on Bottom Layer "Bottom Layer-GND" (solid, remove dead copper, pour order 1003): 75,7225 75,1060 1260,1060 1260,75 3975,75 3975,7225
AGND on Bottom Layer "Bottom Layer-AGND" (solid, remove dead copper, pour order 1002): 75,1035 75,75 1235,75 1235,1035
no net on Top Overlay (solid): 1050,4500 1000,4450 1100,4450
no net on Top Overlay (solid): 1700,4500 1650,4450 1750,4450
no net on Top Overlay (solid): 2350,4500 2300,4450 2400,4450
no net on Top Overlay (solid): 3000,4500 2950,4450 3050,4450

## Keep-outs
Keep-Out Layer:
  circle w10: c3830,4155 r160
  circle w10: c220,4155 r160
  circle w10: c220,7080 r160
  circle w10: c3830,7080 r160
  circle w10: c3830,220 r160
  circle w10: c220,220 r160
  lines w11.81: 50,50 50,7250 4000,7250 4000,50 50,50

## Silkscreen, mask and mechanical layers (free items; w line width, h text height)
Top Overlay:
  text "Weather Channel Station" at 3825,6075 h94.49 r270
  text "MENU" at 1250,3600 h120
Mechanical 1:
  the board outline again, w7.87
Drill Drawing:
  text ".LEGEND" at 150,-1400 h60
  text "Drill Drawing." at 150,-1500 h60

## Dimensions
0,7300 to 4050,7300 on Mechanical 1
0,7300 to 0,0 on Mechanical 1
